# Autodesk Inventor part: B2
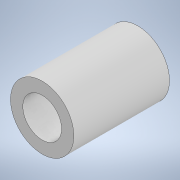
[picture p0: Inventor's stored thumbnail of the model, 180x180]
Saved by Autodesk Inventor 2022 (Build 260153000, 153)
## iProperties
Created: 2024-12
Part Number: B2
Material: 一般
Document SubType Name: Modeling
Designer: jsat7
Density: 1 g/cm^3
Appearance: 既定
Author: jsat7
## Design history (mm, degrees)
sketch "スケッチ1"
  geometry: C1 r 2.45 at (0, 0); C2 r 1.5 at (0, 0); 1 further point
  constraints: 2 centre point, 2 coincident
  dimensions: "d0" = 4.9 diameter of C1; "d1" = 3 diameter of C2
extrude "押し出し1" new body sketch "スケッチ1" distance "d2" = 7.4; taper "d3" = 0 deg
node "ソリッド1"
